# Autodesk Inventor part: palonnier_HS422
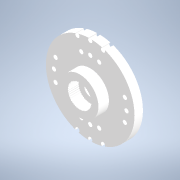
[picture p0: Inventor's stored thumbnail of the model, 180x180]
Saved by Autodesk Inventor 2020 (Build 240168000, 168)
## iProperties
Created: 2012-04
Part Number: palonnier_HS422
Material: Générique
Document SubType Name: Modeling
Designer: bruno
Density: 1 g/cm^3
Appearance: Par défaut
Sending System: SolidWorks 2016
Last Author: Prof
Last Saved: 2018-11-12
Author: bruno
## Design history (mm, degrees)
feature "Extru.-Mince1"
sketch "Esquisse1"
  geometry: C1 r 10.5 at (0, 0) reference; C2 r 1.4 at (0, 0) reference; C3 r 19.029 at (0, 0); 1 further point
  constraints: 1 centre point, 1 coincident
extrude "Extrusion1" cut sketch "Esquisse1" distance "d0" = 10; taper "d1" = 0 deg
node "Solide1"
node "Référence1"
